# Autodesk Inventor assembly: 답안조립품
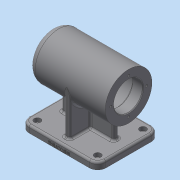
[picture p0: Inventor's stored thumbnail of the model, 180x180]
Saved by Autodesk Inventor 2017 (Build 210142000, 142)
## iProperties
Part Number: 답안조립품
Material: 일반
Document SubType Name: Assembly
Designer: mrc
Author: mrc
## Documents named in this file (2)
- C:\Users\mrc\Desktop\701004V1022\답안조립품.iam
- C:\Users\mrc\Desktop\701004V1022\본체.ipt
